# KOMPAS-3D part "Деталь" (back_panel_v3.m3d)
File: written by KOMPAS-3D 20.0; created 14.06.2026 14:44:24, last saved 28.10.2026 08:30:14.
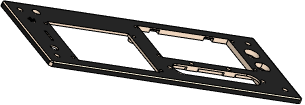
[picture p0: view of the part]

Document properties: Полное имя файла: D:\RicWork\Project-EPS32\box_compas\корпус\back_panel_v3.m3d

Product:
- Part/product: Деталь
    Материал: Фанера, береза,ФСФ ВВ/С ГОСТ 3916.1-2018 (density 760 kg/m3)
    Масса: 0.0216848
  - Body: Тело 9
      Масса: 0.0217905
  - Body: Тело 8
      Масса: 0.0217905
  - Body: Тело 7
      Масса: 0.0217905
  - Body: Тело 6
      Масса: 0.0217905
  - Body: Тело 5
      Масса: 0.0217905
  - Body: Тело 1
      Масса: 0.0217905

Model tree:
1. Эскиз:1
2. Элемент выдавливания:1
     Расстояние 1 = 4
3. Эскиз:5  (with: Элемент выдавливания:1)
4. Элемент выдавливания:5
     Расстояние 2 = 2
5. Эскиз:6  (with: Элемент выдавливания:1, Элемент выдавливания:5)
6. Эскиз:4  (with: Элемент выдавливания:1)
7. Элемент выдавливания:6
     Расстояние 2 = 4
8. Массив по сетке:14  (with: Элемент выдавливания:6, Эскиз:6)  (4 pattern instances)
     Шаг 1 = 196; Угол раствора = -90; Шаг 2 = 60
9. Эскиз:16  (with: Элемент выдавливания:1)
10. Элемент выдавливания:19
     Расстояние 2 = 4
11. Эскиз:17  (with: Элемент выдавливания:1, Элемент выдавливания:19)
12. Элемент выдавливания:23
     Расстояние 2 = 4
13. Эскиз:20  (with: Элемент выдавливания:5, Элемент выдавливания:19)
14. Элемент выдавливания:24
     Расстояние 2 = 1.5
15. Скругление:7  (with: Элемент выдавливания:24)
     Радиус = 3
16. Эскиз:22  (with: Элемент выдавливания:5)
17. Элемент выдавливания:26
     Расстояние 1 = 2
18. Скругление:8  (with: Элемент выдавливания:26)
     Радиус = 0.4
19. Массив по сетке:5  (with: Элемент выдавливания:26, Эскиз:22, Скругление:8, Элемент выдавливания:5)  (7 pattern instances)
     Шаг 1 = 5; Угол раствора = 90
20. Эскиз:25  (with: Элемент выдавливания:5)
21. Элемент выдавливания:28
     Расстояние 1 = 2
22. Скругление:10  (with: Элемент выдавливания:28)
     Радиус = 0.4
23. Массив по сетке:7  (with: Элемент выдавливания:28, Эскиз:25, Скругление:10, Элемент выдавливания:5)  (15 pattern instances)
     Шаг 1 = 5; Угол раствора = 90
24. Массив по концентрической сетке:3  (with: Элемент выдавливания:23, Эскиз:17, Элемент выдавливания:19)  (5 pattern instances)
     Шаг 2 = 360
25. Эскиз:29  (with: Элемент выдавливания:5, Элемент выдавливания:1)
26. Элемент выдавливания:36
     Расстояние 2 = 2
27. Смещенная плоскость:1  (with: Элемент выдавливания:1)
     Расстояние = 13.75
28. Эскиз:32  (with: Элемент выдавливания:36)
29. Элемент вращения:3
     Угол 1 = 360
30. Элемент выдавливания:46
     Расстояние 2 = 4
31. Эскиз:2  (with: Элемент выдавливания:1, Элемент выдавливания:46)
32. Элемент выдавливания:2
     Расстояние 2 = 4
33. Массив по сетке:1  (with: Элемент выдавливания:2, Эскиз:2)  (4 pattern instances)
     Шаг 1 = 83; Угол раствора = 90; Шаг 2 = 37
34. Эскиз:39  (with: Элемент выдавливания:1, Элемент выдавливания:46)
35. Элемент выдавливания:48
     Расстояние 2 = 4
36. Массив по сетке:11  (with: Элемент выдавливания:48, Эскиз:39, Элемент выдавливания:1)  (4 pattern instances)
     Шаг 1 = 75.9; Угол раствора = 90; Шаг 2 = 44.2
37. Эскиз:35  (with: Элемент выдавливания:5, Элемент выдавливания:2, Скругление:7, Элемент выдавливания:26, Скругление:8, Элемент выдавливания:28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)
38. Элемент выдавливания:50
     Расстояние 1 = 2
39. Эскиз:41  (with: Элемент выдавливания:5, Элемент выдавливания:48)
40. Элемент выдавливания:52
     Расстояние 1 = 2
41. Эскиз:42  (with: Элемент выдавливания:1, Элемент выдавливания:46)
42. Элемент выдавливания:55
     Расстояние 2 = 4
43. Эскиз:45  (with: Элемент выдавливания:5, Элемент выдавливания:26)
44. Элемент выдавливания:58
     Расстояние 1 = 2
45. Массив по сетке:12  (with: Элемент выдавливания:58, Эскиз:45)  (3 pattern instances)
     Шаг 1 = 10; Угол раствора = -90
46. Эскиз:46  (with: Элемент выдавливания:5, Элемент выдавливания:28, Элемент выдавливания:1)
47. Элемент выдавливания:59
     Расстояние 1 = 2
48. Массив по сетке:13  (with: Элемент выдавливания:59, Эскиз:46, Элемент выдавливания:1)  (7 pattern instances)
     Шаг 1 = 10; Угол раствора = 90
49. Эскиз:47  (with: Элемент выдавливания:5, Элемент выдавливания:1)
50. Элемент выдавливания:60
     Расстояние 2 = 0.75
51. Фаска:1  (with: Элемент выдавливания:48, Элемент выдавливания:2)
     Угол = 45; Длина 1 = 0.75; Длина 2 = 0.75
52. Эскиз:49  (with: Элемент выдавливания:1, Элемент выдавливания:6, Элемент выдавливания:19, Элемент выдавливания:23, Элемент выдавливания:36, Элемент выдавливания:46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)
53. Эскиз:52  (with: Элемент выдавливания:1, Элемент выдавливания:55)
54. Элемент выдавливания:63
     Расстояние 2 = 2
55. Эскиз:53  (with: Элемент выдавливания:1)
56. Элемент выдавливания:64
     Расстояние 2 = 0.2
57. Скругление:15  (with: Элемент выдавливания:63)
     Радиус = 1
58. Массив по сетке:15  (with: Элемент выдавливания:64, Эскиз:53)  (4 pattern instances)
     Шаг 1 = 196; Угол раствора = -90; Шаг 2 = 60
59. Фаска:2  (with: Элемент выдавливания:50)
     Угол = 45; Длина 1 = 0.4; Длина 2 = 0.4
60. Эскиз:54  (with: Элемент выдавливания:1, Элемент выдавливания:50, Элемент выдавливания:55, Фаска:2)
61. Элемент выдавливания:67
     Расстояние 2 = 2.5
62. Скругление:16  (with: Элемент выдавливания:67, Элемент выдавливания:50, Элемент выдавливания:5)
     Радиус = 1
63. Скругление:17  (with: Элемент выдавливания:1)
     Радиус = 1
64. Скругление:18  (with: Элемент выдавливания:1)  (labels: Фанера, береза,ФСФ ВВ/С ГОСТ 3916.1-2018)
     Радиус = 2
